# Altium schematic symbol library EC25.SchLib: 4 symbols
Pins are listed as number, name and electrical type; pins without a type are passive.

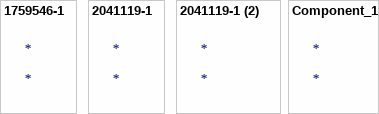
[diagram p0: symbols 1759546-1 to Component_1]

## 1759546-1
designator *
Card Edge Connector, 52 Contact(s), 2 Row(s), Right Angle, 0.031 inch Pitch, Solder Terminal, Locking, Black Insulator; Manufacturer: TE Connectivity; Manufacturer Part Number: 1759546-1; Manufacturer Series: 1759546; Number of Rows Loaded: 2; Board Mounting Option: PEG; Contact Style: BELLOWED TYPE; Dielectric Withstanding Voltage (AC): 300V; Durability: 50Cycles; Insulation Resistance: 500MR; Number Of Connectors: 1; PCB Contact Pattern: STAGGERED; Rated Current (Signal): 500mA; Contact Pattern: RECTANGULAR; Body Breadth: 0.39inch; Body Depth: 0.331inch; Body Length: 1.181inch; Reference Standard: UL; Reliability: COMMERCIAL

## 2041119-1
designator *
Card Edge Connector, 52 Contact(s), 2 Row(s), Female, Right Angle, 0.031 inch Pitch, Surface Mount Terminal, Locking, Black Insulator, Receptacle; Manufacturer: TE Connectivity; Manufacturer Part Number: 2041119-1; Option: General Purpose; Filter Feature: No; Number of Rows Loaded: 2; Number of Contacts: 52

## 2041119-1 (2)
designator *
Card Edge Connector, 52 Contact(s), 2 Row(s), Female, Right Angle, 0.031 inch Pitch, Surface Mount Terminal, Locking, Black Insulator, Receptacle; Manufacturer: TE Connectivity; Manufacturer Part Number: 2041119-1; Option: General Purpose; Filter Feature: No; Number of Rows Loaded: 2; Number of Contacts: 52

## Component_1
designator *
